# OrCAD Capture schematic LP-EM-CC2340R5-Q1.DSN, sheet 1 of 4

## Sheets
1 1_RF: size A3; title: LP-EM-CC2340R5
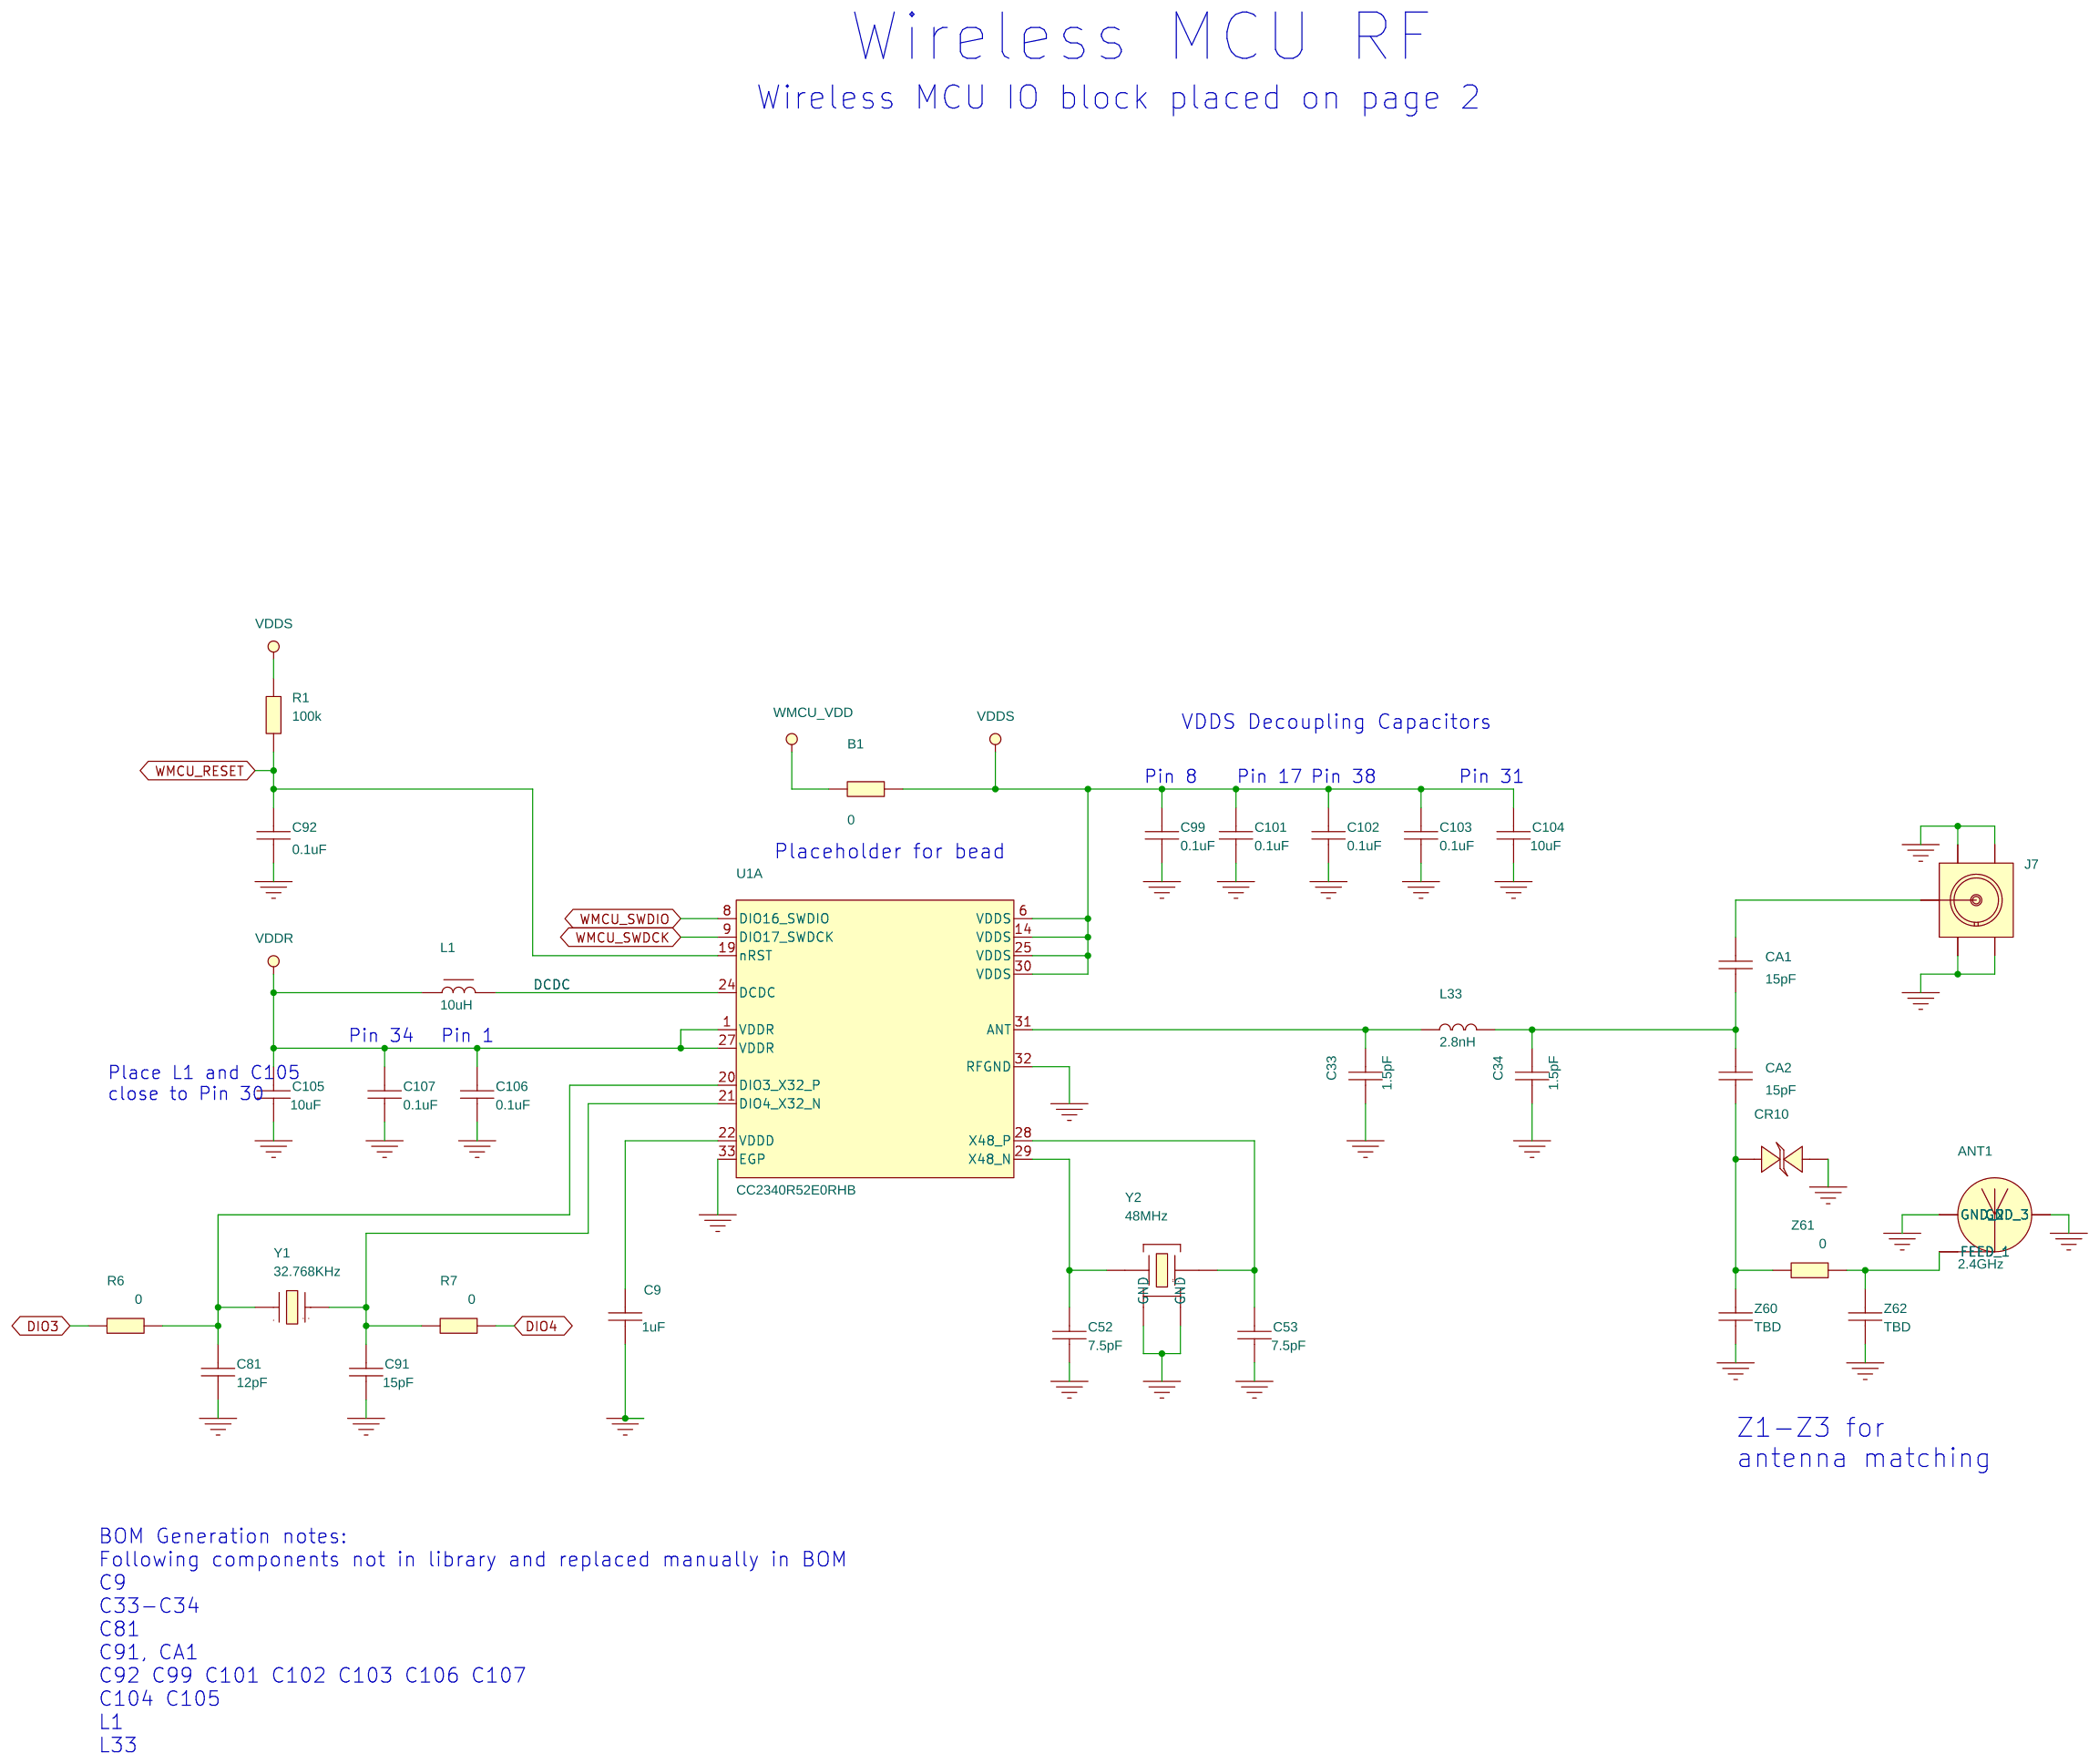
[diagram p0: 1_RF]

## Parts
sheet 1_RF
ANT1  2.4GHz  [ANTENNA_DN007AN]
B1  0  [RESC1608X55A2N]
C9  1uF  [CAPC1005X60B2N]
C33  1.5pF  [CAPC0603X35B2N]
C34  1.5pF  [CAPC0603X35B2N]
C52  7.5pF  [CAPC0603X35B2N]
C53  7.5pF  [CAPC0603X35B2N]
C81  12pF  [CAPC0603X35B2N]
C91  15pF  [CAPC0603X35B2N]
C92  0.1uF  [CAPC0603X35B2N]
C99  0.1uF  [CAPC0603X35B2N]
C101  0.1uF  [CAPC0603X35B2N]
C102  0.1uF  [CAPC0603X35B2N]
C103  0.1uF  [CAPC0603X35B2N]
C104  10uF  [CAPC1608X100A2N]
C105  10uF  [CAPC1608X100A2N]
C106  0.1uF  [CAPC0603X35B2N]
C107  0.1uF  [CAPC0603X35B2N]
CA1  15pF  [CAPC0603X35B2N]
CA2  15pF  [CAPC0603X35B2N]
CR10  TPD1E0B04DPY  [SON65P100X60X45-2A2N]
J7  SMA-10V21-TGG  [HUSTSAN_SMA10V21TGGAN]
L1  10uH  [INDC1608X100A2N]
L33  2.8nH  [INDC0603X33A2N]
R1  100k  [RESC0603X35B2N]
R6  0  [RESC0603X35B2N]
R7  0  [RESC0603X35B2N]
Y1  32.768KHz  [XTAL_TZ3359DAAO73_A2N]
Y2  48MHz  [OSCCC205X165X50-4A2N]
Z60  TBD  [CAPC0603X35B2N]
Z61  0  [RESC0603X35B2N]
Z62  TBD  [CAPC0603X35B2N]
sheet 2_Peripherals
U1  CC2340R52E0RHB  [QFNFC50P500X500X100-33B2N]  (sections A,B)

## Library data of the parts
ANT1 = ANTENNA_DN007: ANTENNA, NON COMPONENT, 2.4GHz INVERTED F ANTENNA, NOT APPLY; Additional Datasheet URL: N/A; AutoDoc File: http://notefied-dynamic-precision.com/DB/Apps/Desktop/Item/Object.aspx?id=85542; Budget Currency: N/A; Budget Price: N/A; CLASS: DISCRETE; Country of Origin: Missing Info; Datasheet URL: http://www.ti.com/; Datasheet URL 1: http://www.ti.com/lit/er/swrz002d/swrz002d.pdf; Datasheet URL 2: http://www.ti.com/lit/ds/symlink/cc2500.pdf; Definied Quality: INDUSTRIAL; Esd Level: HBM 500V; Exclusive for Customers: TEXAS INSTRUMENTS NORWAY; FPLIST: ANTENNA_DN007N,ANTENNA_DN007AN,; MPN: DN007; MPN Status: ACTIVE; MSL: N/A; MTBF: N/A; MTBF Standard: N/A; Manufacturer: TEXAS INSTRUMENTS; Mass: N/A; Max Oper Temp: +85DEGC; Maximum Operating Temperature: +85DEGC; Min Oper Temp: -40DEGC; Minimum Operating Temperature: -40DEGC; Mounting Type: NOT APPLY; NOTE Status: PREFERRED; NOTEfied URL: https://notefied-dynamic-precision.com/NOTEfiedWebInterface/part/show?partNumber=13-00347; Notes: Custom Item; Old Footprint: ANTENNA_DN007N,ANTENNA_DN007AN; Packing Size: N/A; Packing Type: Missing Info; Part Number: 13-00347; Part Type: Mechanic|ANTENNA|NON COMPONENT; ROHS: Not Applicable; Revision: R026; RoHS Status: LEADED; Status: Released; Texas Part Status: Under Review; Type: Mechanic; Vendor: TEXAS INSTRUMENTS; Vendor Part Number: DN007; Vendor Part Status: Active; WEIGHT: N/A
B1 = RESISTOR: RESISTOR, THICK FILM, 0, 0R/+0.05R, 1A, -55DEGC/+155DEGC, 0603, SMD; ALT_SYMBOLS: RESC1608X55A2L,RESC1608X55A2M; Additional Datasheet URL: https://www.koaspeer.com/products/resistors/general-purpose/rk73z/; Budgetary Price: 0.003 EUR; Country of Origin: China,Japan,Malaysia; Datasheet URL: https://www.koaspeer.com/pdfs/RK73Z.pdf; Lead Time: 46; Mass: 0.00214g; Maximum Operating Temperature: +155DEGC; Maximum Temperature Coefficient: N/A; Maximum Tolerance: +0.05R; Minimum Operating Temperature: -55DEGC; Minimum Temperature Coeficient: N/A; Minimum Tolerance: 0R; Mounting Type: SMD; NOTEfied URL: https://notefied-dynamic-precision.com/NOTEfiedWebInterface/part/show?partNumber=01-01788; PCB Package: 0603; Packing Size: 5000; Packing Type: Tape & Reel; Part Number: 01-01788; Part Type: Resistor|0603|JUMPER; ROHS: Exempt; Rated Current: 1A; Rated Power: 0.1; Rated Voltage: N/A; Resistor Type: THICK FILM; Revision: R048; Status: Released; Type: Resistor; Vendor: KOA SPEER; Vendor Part Number: RK73Z1JTTD; Vendor Part Status: Active
C9 = CAPACITOR: CAPACITOR, CERAMIC X7R, 1uF, 10V, -10%/+10%, -55DEGC/+125DEGC, 0402, SMD; Additional Datasheet URL: https://search.murata.co.jp/Ceramy/image/img/A01X/G101/ENG/GRM155Z71A105KE01-01A.pdf; Datasheet URL: https://www.murata.com/-/media/webrenewal/support/library/catalog/products/capacitor/ceramiccapacitor/c02e.ashx; Dielectric Type: X7R; Mass: 0.0016g; Maximum Operating Temperature: +125DEGC; Maximum Tolerance: +10%; Minimum Operating Temperature: -55DEGC; Minimum Tolerance: -10%; Mounting Type: SMD; NOTEfied URL: https://notefied-dynamic-precision.com/NOTEfiedWebInterface/part/show?partNumber=02-10417; PCB Package: 0402; Packing Size: 10000; Packing Type: Tape & Reel; Part Number: 02-10417; Part Type: Capacitor|CERAMIC|0402|STANDARD; REACH/SVHC Compliance: Compliant; REACH/SVHC Details: SVHC List Version Jul 08, 2021; REACH/SVHC Source: REACH Declaration; REACH/SVHC Status: Unaffected; ROHS: Compliant; Rated Voltage: 10V; Revision: R001; Status: Released; Texas Part Status: Under Review; Type: Capacitor; Vendor: MURATA; Vendor Part Number: GRM155Z71A105KE01D; Vendor Part Status: Active
C33 C34 = CAPACITOR: CAPACITOR, CERAMIC C0G/NP0, 0.9pF, 50V, -0.1pF/+0.1pF, -55DEGC/+125DEGC, 0201, SMD; ALT_SYMBOLS: CAPC0603X35B2L,CAPC0603X35B2M; Additional Datasheet URL: https://search.murata.co.jp/Ceramy/image/img/A01X/G101/ENG/GRM0335C1HR90BA01-01A.pdf; AutoDoc File: https://notefied-dynamic-precision.com/DB/Apps/Desktop/Item/Object.aspx?id=113355; BU Name: TEXAS INSTRUMENTS NORWAY; Budget Currency: EUR; Budget Price: 0.006; Budgetary Price: 0.00272 USD; Capacitance: 0.9pF; Country of Origin: Missing Info; Datasheet URL: https://www.murata.com/-/media/webrenewal/support/library/catalog/products/capacitor/ceramiccapacitor/c02e.ashx; Datasheet URL 1: http://psearch.murata.com/capacitor/product/GRM1555C1H1R0CA01%23.pdf; Datasheet URL 2: http://search.murata.co.jp/Ceramy/image/img/w_hinm/L0005E.pdf; Dielectric Type: C0G/NP0; Lead Time: 11; MPN: GRM1555C1H1R0CA01D; MPN Status: ACTIVE; Manufacturer: MURATA; Mass: 0.00033g; Max Oper Temp: +125DEGC; Max Tol: +0.25pF; Maximum Operating Temperature: +125DEGC; Maximum Tolerance: +0.1pF; Min Oper Temp: -55DEGC; Min Tol: -0.25pF; Minimum Operating Temperature: -55DEGC; Minimum Tolerance: -0.1pF; Mounting Type: SMD; NOTE Status: PREFERRED; NOTEfied URL: https://notefied-dynamic-precision.com/NOTEfiedWebInterface/part/show?partNumber=02-06123; Old Footprint: CAPC1005X60N; PCB Package: 0201; Packing Size: 50000; Packing Type: Tape & Reel; Part Number: 02-06123; Part Type: Capacitor|CERAMIC|0201|STANDARD; REACH/SVHC Compliance: Compliant; REACH/SVHC Details: SVHC List Version Jul 7, 2017; REACH/SVHC Source: REACH Declaration; REACH/SVHC Status: Unaffected; REACH/SVHC_COMPLIANCE: COMPLIANT; REACH/SVHC_DETAILS: SVHC LIST VERSION Dec 17, 2015; REACH/SVHC_SOURCE: REACH DECLARATION; REACH/SVHC_STATUS: UNAFFECTED; ROHS: Compliant; Rated Voltage: 50V; Revision: R027; RoHS Status: ROHS_COMPLIANT; Rtd Voltage: 50V; Status: Released; Texas Part Status: Under Review; Type: Capacitor; Vendor: MURATA; Vendor Part Number: GRM0335C1HR90BA01J; Vendor Part Status: Active; WEIGHT: 0.0016g
C52 C53 = CAPACITOR: CAPACITOR, CERAMIC C0G/NP0, 7.5pF, 50V, -0.1pF/+0.1pF, -55DEGC/+125DEGC, 0201, SMD; ALT_SYMBOLS: CAPC0603X35B2L,CAPC0603X35B2M; Additional Datasheet URL: https://search.murata.co.jp/Ceramy/image/img/A01X/G101/ENG/GRM0335C1H7R5BA01-01A.pdf; Budgetary Price: 0.00221 USD; Country of Origin: Missing Info; Datasheet URL: https://www.murata.com/-/media/webrenewal/support/library/catalog/products/capacitor/mlcc/c02e.ashx?la=en-gb; Dielectric Type: C0G/NP0; Lead Time: 11; Mass: 0.00033g; Maximum Operating Temperature: +125DEGC; Maximum Tolerance: +0.1pF; Minimum Operating Temperature: -55DEGC; Minimum Tolerance: -0.1pF; Mounting Type: SMD; NOTEfied URL: https://notefied-dynamic-precision.com/NOTEfiedWebInterface/part/show?partNumber=02-06189; PCB Package: 0201; Packing Size: 50000; Packing Type: Tape & Reel; Part Number: 02-06189; Part Type: Capacitor|CERAMIC|0201|STANDARD; REACH/SVHC Compliance: Compliant; REACH/SVHC Details: SVHC List Version Jul 7, 2017; REACH/SVHC Source: REACH Declaration; REACH/SVHC Status: Unaffected; ROHS: Compliant; Rated Voltage: 50V; Revision: R025; Status: Released; Texas Part Status: Under Review; Type: Capacitor; Vendor: MURATA; Vendor Part Number: GRM0335C1H7R5BA01J; Vendor Part Status: Active
C81 = CAPACITOR: CAPACITOR, CERAMIC C0G/NP0, 12pF, 50V, -2%/+2%, -55DEGC/+125DEGC, 0201, SMD; ALT_SYMBOLS: CAPC0603X35B2L,CAPC0603X35B2M; Additional Datasheet URL: https://search.murata.co.jp/Ceramy/image/img/A01X/G101/ENG/GRM0335C1H120GA01-01A.pdf; AutoDoc File: https://notefied-dynamic-precision.com/DB/Apps/Desktop/Item/Object.aspx?id=113345; BU Name: TEXAS INSTRUMENTS NORWAY; Budget Currency: EUR; Budget Price: 0.007; Budgetary Price: 0.00506 USD; Datasheet URL: https://www.murata.com/-/media/webrenewal/support/library/catalog/products/capacitor/ceramiccapacitor/c02e.ashx?la=en-gb&cvid=20210120024548000000; Datasheet URL 1: http://psearch.murata.com/capacitor/product/GRM1555C1H120JA01%23.pdf; Datasheet URL 2: http://search.murata.co.jp/Ceramy/image/img/w_hinm/L0005E.pdf; Definied Quality: INDUSTRIAL; Dielectric Type: C0G/NP0; Esd Level: N/A; Lead Time: 23; LifeCycle Status: ACTIVE; MPN: CAPACITOR_0402_12pF_C0G/NP0_M_+/-5%_50V; MPN Status: ACTIVE; MSL: N/A; MTBF: N/A; MTBF Standard: N/A; Manufacturer: MANUFACTURER SELECTION; Mass: 0.00033g; Max Oper Temp: +125DEGC; Max Tol: +5%; Maximum Operating Temperature: +125DEGC; Maximum Tolerance: +2%; Min Oper Temp: -55DEGC; Min Tol: -5%; Minimum Operating Temperature: -55DEGC; Minimum Tolerance: -2%; Mounting Type: SMD; NOTE Status: PREFERRED; NOTEfied URL: https://notefied-dynamic-precision.com/NOTEfiedWebInterface/part/show?partNumber=02-10307; Old Footprint: CAPC1005X60N; PCB Package: 0201; Packing Size: 15000; Packing Type: Tape & Reel; Part Number: 02-10307; Part Type: Capacitor|CERAMIC|0201|STANDARD; REACH/SVHC Compliance: Compliant; REACH/SVHC Details: SVHC List Version Jan 19, 2021; REACH/SVHC Source: REACH Declaration; REACH/SVHC Status: Unaffected; REACH/SVHC_COMPLIANCE: COMPLIANT; REACH/SVHC_DETAILS: SVHC LIST VERSION Dec 17, 2015; REACH/SVHC_SOURCE: REACH DECLARATION; REACH/SVHC_STATUS: UNAFFECTED; ROHS: Compliant; Rated Voltage: 50V; Revision: R001; RoHS Status: ROHS_COMPLIANT; Rtd Voltage: 50V; Status: Released; Texas Part Status: Under Review; Type: Capacitor; Vendor: MURATA; Vendor Part Number: GRM0335C1H120GA01D; Vendor Part Status: Active; WEIGHT: 0.0016g
C91 = CAPACITOR: CAPACITOR, CERAMIC C0G/NP0, 15pF, 50V, -2%/+2%, -55DEGC/+125DEGC, 0201, SMD; ALT_SYMBOLS: CAPC0603X35B2L,CAPC0603X35B2M; Additional Datasheet URL: https://search.murata.co.jp/Ceramy/image/img/A01X/G101/ENG/GRM0335C1H150GA01-01A.pdf; AutoDoc File: https://notefied-dynamic-precision.com/DB/Apps/Desktop/Item/Object.aspx?id=114571; BU Name: TEXAS INSTRUMENTS NORWAY; Budget Currency: EUR; Budget Price: 0.006; Budgetary Price: 0.0032 USD; Client Status: UNDER_REVIEW; Datasheet URL: https://www.murata.com/-/media/webrenewal/support/library/catalog/products/capacitor/mlcc/c02e.ashx?la=en-gb; Datasheet URL 1: http://psearch.murata.com/capacitor/product/GRM1555C1H150JA01%23.pdf; Datasheet URL 2: http://psearch.en.murata.com/capacitor/product/GRM1555C1H150JA01%23.html; Definied Quality: INDUSTRIAL; Dielectric Type: C0G/NP0; Esd Level: N/A; Lead Time: 11; LifeCycle Status: ACTIVE; MPN: CAPACITOR_0402_12pF_C0G/NP0_M_+/-5%_50V; MPN Status: ACTIVE; MSL: N/A; MTBF: N/A; MTBF Standard: N/A; Manufacturer: MANUFACTURER SELECTION; Mass: 0.00033g; Max Oper Temp: +125DEGC; Max Tol: +5%; Maximum Operating Temperature: +125DEGC; Maximum Tolerance: +2%; Min Oper Temp: -55DEGC; Min Tol: -5%; Minimum Operating Temperature: -55DEGC; Minimum Tolerance: -2%; Mounting Type: SMD; NOTE Status: PREFERRED; NOTEfied URL: https://notefied-dynamic-precision.com/NOTEfiedWebInterface/part/show?partNumber=02-09323; Old Footprint: CAPC1005X60N; PCB Package: 0201; Packing Size: 15000; Packing Type: Tape & Reel; Part Number: 02-09323; Part Type: Capacitor|CERAMIC|0201|STANDARD; REACH/SVHC Compliance: Compliant; REACH/SVHC Details: SVHC List Version Jan 15, 2019; REACH/SVHC Source: REACH Declaration; REACH/SVHC Status: Unaffected; REACH/SVHC_COMPLIANCE: COMPLIANT; REACH/SVHC_DETAILS: SVHC List Version Jan 12, 2017; REACH/SVHC_SOURCE: REACH DECLARATION; REACH/SVHC_STATUS: UNAFFECTED; ROHS: Compliant; Rated Voltage: 50V; Revision: R008; RoHS Status: ROHS_COMPLIANT; Rtd Voltage: 50V; Status: Released; Texas Part Status: Under Review; Type: Capacitor; Vendor: MURATA; Vendor Part Number: GRM0335C1H150GA01D; Vendor Part Status: Active; WEIGHT: 0.0016g
C92 = CAPACITOR: CAPACITOR, CERAMIC X7S, 0.1uF, 10V, -10%/+10%, -55DEGC/+125DEGC, 0201, SMD; ALT_SYMBOLS: CAPC0603X35B2L,CAPC0603X35B2M; Additional Datasheet URL: https://search.murata.co.jp/Ceramy/image/img/A01X/G101/ENG/GRM033C71A104KE14-01A.pdf; AutoDoc File: https://notefied-dynamic-precision.com/DB/Apps/Desktop/Item/Object.aspx?id=115293; BU Name: TEXAS INSTRUMENTS NORWAY; Budgetary Price: 0.01328 USD; Client Status: UNDER_REVIEW; Datasheet URL: https://www.murata.com/-/media/webrenewal/support/library/catalog/products/capacitor/ceramiccapacitor/c02e.ashx?la=en-gb; Datasheet URL 1: http://psearch.en.murata.com/capacitor/product/GRM155R71E104KE14%23.pdf; Datasheet URL 2: http://search.murata.co.jp/Ceramy/image/img/w_hinm/L0005E.pdf; Dielectric Type: X7S; Lead Time: 23; LifeCycle Status: ACTIVE; MPN: GRM155R70J104KA01D; MPN Status: ACTIVE; Manufacturer: MURATA; Mass: 0.00033g; Max Oper Temp: +125DEGC; Max Tol: +10%; Maximum Operating Temperature: +125DEGC; Maximum Tolerance: +10%; Min Oper Temp: -55DEGC; Min Tol: -10%; Minimum Operating Temperature: -55DEGC; Minimum Tolerance: -10%; Mounting Type: SMD; NOTE Status: PREFERRED; NOTEfied URL: https://notefied-dynamic-precision.com/NOTEfiedWebInterface/part/show?partNumber=02-10308; Old Footprint: CAPC1005X60N,0402; PCB Package: 0201; Packing Size: 15000; Packing Type: Tape & Reel; Part Number: 02-10308; Part Type: Capacitor|CERAMIC|0201|STANDARD; REACH/SVHC Compliance: Compliant; REACH/SVHC Details: SVHC List Version Jan 19, 2021; REACH/SVHC Source: REACH Declaration; REACH/SVHC Status: Unaffected; REACH/SVHC_COMPLIANCE: COMPLIANT; REACH/SVHC_DETAILS: SVHC LIST VERSION Jun 20, 2016; REACH/SVHC_SOURCE: REACH DECLARATION; REACH/SVHC_STATUS: UNAFFECTED; ROHS: Compliant; Rated Voltage: 10V; Revision: R001; RoHS Status: ROHS_COMPLIANT; Rtd Voltage: 25V; Status: Released; Texas Part Status: Under Review; Type: Capacitor; Vendor: MURATA; Vendor Part Number: GRM033C71A104KE14D; Vendor Part Status: Active; WEIGHT: 0.0016g
C99 C101-C103 C106 C107 = CAPACITOR: CAPACITOR, CERAMIC X7S, 0.1uF, 10V, -10%/+10%, -55DEGC/+125DEGC, 0201, SMD; ALT_SYMBOLS: CAPC0603X35B2L,CAPC0603X35B2M; Additional Datasheet URL: https://search.murata.co.jp/Ceramy/image/img/A01X/G101/ENG/GRM033C71A104KE14-01A.pdf; AutoDoc File: https://notefied-dynamic-precision.com/DB/Apps/Desktop/Item/Object.aspx?id=115293; BU Name: TEXAS INSTRUMENTS NORWAY; Budgetary Price: 0.01328 USD; Client Status: UNDER_REVIEW; Datasheet URL: https://www.murata.com/-/media/webrenewal/support/library/catalog/products/capacitor/ceramiccapacitor/c02e.ashx; Datasheet URL 1: http://psearch.en.murata.com/capacitor/product/GRM155R71E104KE14%23.pdf; Datasheet URL 2: http://search.murata.co.jp/Ceramy/image/img/w_hinm/L0005E.pdf; Dielectric Type: X7S; Lead Time: 23; LifeCycle Status: ACTIVE; MPN: GRM155R70J104KA01D; MPN Status: ACTIVE; Manufacturer: MURATA; Mass: 0.00033g; Max Oper Temp: +125DEGC; Max Tol: +10%; Maximum Operating Temperature: +125DEGC; Maximum Tolerance: +10%; Min Oper Temp: -55DEGC; Min Tol: -10%; Minimum Operating Temperature: -55DEGC; Minimum Tolerance: -10%; Mounting Type: SMD; NOTE Status: PREFERRED; NOTEfied URL: https://notefied-dynamic-precision.com/NOTEfiedWebInterface/part/show?partNumber=02-10308; Old Footprint: CAPC1005X60N,0402; PCB Package: 0201; Packing Size: 15000; Packing Type: Tape & Reel; Part Number: 02-10308; Part Type: Capacitor|CERAMIC|0201|STANDARD; REACH/SVHC Compliance: Compliant; REACH/SVHC Details: SVHC List Version Jan 19, 2021; REACH/SVHC Source: REACH Declaration; REACH/SVHC Status: Unaffected; REACH/SVHC_COMPLIANCE: COMPLIANT; REACH/SVHC_DETAILS: SVHC LIST VERSION Jun 20, 2016; REACH/SVHC_SOURCE: REACH DECLARATION; REACH/SVHC_STATUS: UNAFFECTED; ROHS: Compliant; Rated Voltage: 10V; Revision: R003; RoHS Status: ROHS_COMPLIANT; Rtd Voltage: 25V; Status: Released; Texas Part Status: Under Review; Type: Capacitor; Vendor: MURATA; Vendor Part Number: GRM033C71A104KE14D; Vendor Part Status: Active; WEIGHT: 0.0016g
C104 = CAPACITOR: CAPACITOR, CERAMIC X7R, 10uF, 10V, -10%/+10%, -55DEGC/+125DEGC, 0603, SMD; ALT_SYMBOLS: CAPC1608X100A2L,CAPC1608X100A2M; Additional Datasheet URL: https://search.murata.co.jp/Ceramy/image/img/A01X/G101/ENG/GRM188Z71A106KA73-01A.pdf; Datasheet URL: https://www.murata.com/-/media/webrenewal/support/library/catalog/products/capacitor/ceramiccapacitor/c02e.ashx; Dielectric Type: X7R; Mass: 0.0091g; Maximum Operating Temperature: +125DEGC; Maximum Tolerance: +10%; Minimum Operating Temperature: -55DEGC; Minimum Tolerance: -10%; Mounting Type: SMD; NOTEfied URL: https://notefied-dynamic-precision.com/NOTEfiedWebInterface/part/show?partNumber=02-10418; PCB Package: 0603; Packing Size: 4000; Packing Type: Tape & Reel; Part Number: 02-10418; Part Type: Capacitor|CERAMIC|0603|STANDARD; REACH/SVHC Compliance: Compliant; REACH/SVHC Details: SVHC List Version Jul 08, 2021; REACH/SVHC Source: REACH Declaration; REACH/SVHC Status: Unaffected; ROHS: Compliant; Rated Voltage: 10V; Revision: R001; Status: Released; Texas Part Status: Under Review; Type: Capacitor; Vendor: MURATA; Vendor Part Number: GRM188Z71A106KA73D; Vendor Part Status: Active
C105 = CAPACITOR: CAPACITOR, CERAMIC X7R, 10uF, 10V, -10%/+10%, -55DEGC/+125DEGC, 0603, SMD; ALT_SYMBOLS: CAPC1608X100A2L,CAPC1608X100A2M; Additional Datasheet URL: https://search.murata.co.jp/Ceramy/image/img/A01X/G101/ENG/GRM188Z71A106KA73-01A.pdf; Datasheet URL: https://www.murata.com/-/media/webrenewal/support/library/catalog/products/capacitor/ceramiccapacitor/c02e.ashx; Dielectric Type: X7R; Mass: 0.0091g; Maximum Operating Temperature: +125DEGC; Maximum Tolerance: +10%; Minimum Operating Temperature: -55DEGC; Minimum Tolerance: -10%; Mounting Type: SMD; NOTEfied URL: https://notefied-dynamic-precision.com/NOTEfiedWebInterface/part/show?partNumber=02-10418; PCB Package: 0603; Packing Size: 4000; Packing Type: Tape & Reel; Part Number: 02-10418; Part Type: Capacitor|CERAMIC|0603|STANDARD; REACH/SVHC Compliance: Compliant; REACH/SVHC Details: SVHC List Version Jul 08, 2021; REACH/SVHC Source: REACH Declaration; REACH/SVHC Status: Unaffected; ROHS: Compliant; Rated Voltage: 10V; Revision: R002; Status: Released; Texas Part Status: Under Review; Type: Capacitor; Vendor: MURATA; Vendor Part Number: GRM188Z71A106KA73D; Vendor Part Status: Active
CA1 CA2 = CAPACITOR: CAPACITOR, CERAMIC C0G/NP0, 15pF, 50V, -2%/+2%, -55DEGC/+125DEGC, 0201, SMD; ALT_SYMBOLS: CAPC0603X35B2L,CAPC0603X35B2M; Additional Datasheet URL: https://search.murata.co.jp/Ceramy/image/img/A01X/G101/ENG/GRM0335C1H150GA01-01A.pdf; AutoDoc File: https://notefied-dynamic-precision.com/DB/Apps/Desktop/Item/Object.aspx?id=113345; BU Name: TEXAS INSTRUMENTS NORWAY; Budget Currency: EUR; Budget Price: 0.007; Budgetary Price: 0.0032 USD; Datasheet URL: https://www.murata.com/-/media/webrenewal/support/library/catalog/products/capacitor/ceramiccapacitor/c02e.ashx; Datasheet URL 1: http://psearch.murata.com/capacitor/product/GRM1555C1H120JA01%23.pdf; Datasheet URL 2: http://search.murata.co.jp/Ceramy/image/img/w_hinm/L0005E.pdf; Definied Quality: INDUSTRIAL; Dielectric Type: C0G/NP0; Esd Level: N/A; Lead Time: 11; LifeCycle Status: ACTIVE; MPN: CAPACITOR_0402_12pF_C0G/NP0_M_+/-5%_50V; MPN Status: ACTIVE; MSL: N/A; MTBF: N/A; MTBF Standard: N/A; Manufacturer: MANUFACTURER SELECTION; Mass: 0.00033g; Max Oper Temp: +125DEGC; Max Tol: +5%; Maximum Operating Temperature: +125DEGC; Maximum Tolerance: +2%; Min Oper Temp: -55DEGC; Min Tol: -5%; Minimum Operating Temperature: -55DEGC; Minimum Tolerance: -2%; Mounting Type: SMD; NOTE Status: PREFERRED; NOTEfied URL: https://notefied-dynamic-precision.com/NOTEfiedWebInterface/part/show?partNumber=02-09323; Old Footprint: CAPC1005X60N; PCB Package: 0201; Packing Size: 15000; Packing Type: Tape & Reel; Part Number: 02-09323; Part Type: Capacitor|CERAMIC|0201|STANDARD; REACH/SVHC Compliance: Compliant; REACH/SVHC Details: SVHC List Version Jan 15, 2019; REACH/SVHC Source: REACH Declaration; REACH/SVHC Status: Unaffected; REACH/SVHC_COMPLIANCE: COMPLIANT; REACH/SVHC_DETAILS: SVHC LIST VERSION Dec 17, 2015; REACH/SVHC_SOURCE: REACH DECLARATION; REACH/SVHC_STATUS: UNAFFECTED; ROHS: Compliant; Rated Voltage: 50V; Revision: R010; RoHS Status: ROHS_COMPLIANT; Rtd Voltage: 50V; Status: Released; Texas Part Status: Under Review; Type: Capacitor; Vendor: MURATA; Vendor Part Number: GRM0335C1H150GA01D; Vendor Part Status: Active; WEIGHT: 0.0016g
CR10 = DIODE_TVS_BIDIR_S: DIODE, PROTECTION, TVS, BID, 6.7V, 15W, -40DEGC/+125DEGC, X1SON2, SMD; Additional Datasheet URL: https://www.ti.com/lit/ml/mpss034c/mpss034c.pdf; AutoDoc File: https://notefied-dynamic-precision.com/DB/Apps/Desktop/Item/Object.aspx?id=118028; BU Name: DYNAMIC PRECISION GDANSK; Budget Currency: USD; Budget Price: 0.08; Budgetary Price: 0.144 USD; Client Status: UNDER_REVIEW; Datasheet URL: https://www.ti.com/lit/gpn/tpd1e0b04; Datasheet URL 1: http://www.ti.com/lit/ds/symlink/tpd1e0b04.pdf; Datasheet URL 2: http://www.ti.com/lit/ml/mpss034c/mpss034c.pdf; Lead Time: 12; Mass: 0.0031g; Max Oper Temp: +125DEGC; Maximum Operating Temperature: +125DEGC; Min Oper Temp: -40DEGC; Minimum Operating Temperature: -40DEGC; Mounting Type: SMD; NOTEfied URL: https://notefied-dynamic-precision.com/NOTEfiedWebInterface/part/show?partNumber=14-06704; PCB Package: SON2; Packing Size: 10000; Packing Type: Tape & Reel; Part Number: 14-06704; Part Type: Diode|PROTECTION; REACH/SVHC Compliance: Compliant; REACH/SVHC Details: SVHC List Version Jan 12, 2017; REACH/SVHC Source: REACH Declaration; REACH/SVHC Status: Unaffected; ROHS: Compliant; Rated Power: 15W; Rated Voltage: 6.7V; Revision: R023; RoHS Status: ROHS_COMPLIANT; Rtd Power: 15W; Rtd Voltage: 6.7V; Status: Released; Texas Part Status: Under Review; Type: Diode; Vendor: TEXAS INSTRUMENTS; Vendor Part Number: TPD1E0B04DPYR; Vendor Part Status: Active; Weight: 0.0031g
J7 = CONN_COAX_1_4: CONNECTOR, COAX, RF, FEMALE, STRAIGHT, 1 PIN, SMD; ALT_SYMBOLS: HUSTSAN_SMA10V21TGGL,HUSTSAN_SMA10V21TGGM; Additional Datasheet URL: http://www.hustsan.com.tw/cgi-bin/productfn/pdt_detail_lst.pl?ProdID=143; AutoDoc File: https://notefied-dynamic-precision.com/DB/Apps/Desktop/Item/Object.aspx?id=84956; BU Name: DYNAMIC PRECISION GDANSK; Budget Currency: N/A; Budget Price: N/A; Client Status: UNDER_REVIEW; Country of Origin: Taiwan; Datasheet URL: http://www.hustsan.com.tw/uploaddir/product/SMA-10V21.pdf; Datasheet URL 1: http://www.hustsan.com.tw/uploaddir/product/SMA-10V21.pdf; Datasheet URL 2: http://www.hustsan.com.tw/cgi-bin/productfn/pdt_detail_lst.pl?ProdID=143; FPLIST: HUSTSAN_SMA10V21TGGAN,HUSTSAN_SMA10V21TGGN; Mass: N/A; Mounting Type: SMD; NOTEfied URL: https://notefied-dynamic-precision.com/NOTEfiedWebInterface/part/show?partNumber=06-02188; No Of Pos: 1; Number of Positions: 1; Packing Size: 350; Packing Type: Tape & Reel; Part Number: 06-02188; Part Type: Connector|COAX|RF; REACH/SVHC Compliance: Compliant; REACH/SVHC Details: SVHC List Version Jun 20, 2016; REACH/SVHC Source: REACH Declaration; REACH/SVHC Status: Unaffected; REACH/SVHC_COMPLIANCE: COMPLIANT; REACH/SVHC_DETAILS: SVHC LIST VERSION Jan 12, 2016; REACH/SVHC_SOURCE: REACH DECLARATION; REACH/SVHC_STATUS: UNAFFECTED; ROHS: Compliant; Revision: R011; RoHS Status: ROHS_COMPLIANT; Status: Released; Texas Part Status: Under Review; Type: Connector; Vendor: HUS-TSAN; Vendor Part Status: Active; Weight: N/A
L1 = IND_CORE: INDUCTOR, STANDARD, CHIP, FERRITE CORE, 10uH, -20%/+20%, 0.1A, -55DEGC/+125DEGC, 0603, SMD; ALT_SYMBOLS: INDC1608X100A2L,INDC1608X100A2M; Additional Datasheet URL: N/A; Datasheet URL: https://search.murata.co.jp/Ceramy/image/img/P02/JELF243B-0086.pdf; Frequency: 32MHz; Mass: 0.005g; Maximum Operating Temperature: +125DEGC; Maximum Tolerance: +20%; Minimum Operating Temperature: -55DEGC; Minimum Tolerance: -20%; Mounting Type: SMD; NOTEfied URL: https://notefied-dynamic-precision.com/NOTEfiedWebInterface/part/show?partNumber=03-08367; PCB Package: 0603; Packing Size: 4000; Packing Type: Tape & Reel; Part Number: 03-08367; Part Type: Inductor|STANDARD|CHIP|0603; REACH/SVHC Compliance: Missing Info; REACH/SVHC Details: Jul 08, 2021 (219); REACH/SVHC Source: N/A; REACH/SVHC Status: Unaffected; ROHS: Compliant; Resistance: 1.05; Revision: R002; Status: Released; Texas Part Status: Under Review; Type: Inductor; Vendor: MURATA; Vendor Part Number: LQM18DN100M70L; Vendor Part Status: Active
L33 = INDUCTOR: INDUCTOR, RF, CHIP, NON-MAGNETIC CORE, 2.8nH, -0.1nH/+0.1nH, 0.5A, -55DEGC/+125DEGC, 0201, SMD; ALT_SYMBOLS: INDC0603X33A2L,INDC0603X33A2M; Additional Datasheet URL: https://search.murata.co.jp/Ceramy/image/img/P02/JELF243C-0015.pdf; Country of Origin: Missing Info; Datasheet URL: https://www.murata.com/-/media/webrenewal/support/library/catalog/products/inductor/chip/o05e.ashx; Frequency: 9.5GHz; Mass: 0.0002g; Maximum Operating Temperature: +125DEGC; Maximum Tolerance: +0.1nH; Minimum Operating Temperature: -55DEGC; Minimum Tolerance: -0.1nH; Mounting Type: SMD; NOTEfied URL: https://notefied-dynamic-precision.com/NOTEfiedWebInterface/part/show?partNumber=03-06931; PCB Package: 0201; Packing Size: 50000; Packing Type: Tape & Reel; Part Number: 03-06931; Part Type: Inductor|RF|CHIP|0201; ROHS: Compliant; Resistance: 0.2; Revision: R022; Status: Released; Texas Part Status: Under Review; Type: Inductor; Vendor: MURATA; Vendor Part Number: LQP03TN2N8B02J; Vendor Part Status: Active
R1 = RESISTOR: RESISTOR, THICK FILM, 100k, -5%/+5%, 0.05W, 30V, -55DEGC/+155DEGC, 0201, SMD; ALT_SYMBOLS: RESC0603X35B2L,RESC0603X35B2M; Additional Datasheet URL: N/A; Budgetary Price: 0.005 EUR; Country of Origin: Taiwan; Datasheet URL: https://www.vishay.com/docs/20052/crcw0201e3.pdf; Lead Time: 20; Mass: 0.00017g; Maximum Operating Temperature: +155DEGC; Maximum Temperature Coefficient: +200PPM/DEGC; Maximum Tolerance: +5%; Minimum Operating Temperature: -55DEGC; Minimum Temperature Coeficient: -200PPM/DEGC; Minimum Tolerance: -5%; Mounting Type: SMD; NOTEfied URL: https://notefied-dynamic-precision.com/NOTEfiedWebInterface/part/show?partNumber=01-04220; PCB Package: 0201; Packing Size: 10000; Packing Type: Tape & Reel; Part Number: 01-04220; Part Type: Resistor|0201|STANDARD; REACH/SVHC Compliance: Compliant; REACH/SVHC Details: SVHC List Version Dec 17, 2015; REACH/SVHC Source: Material Declaration; REACH/SVHC Status: Unaffected; ROHS: Exempt; Rated Current: N/A; Rated Power: 0.05W; Rated Voltage: 30V; Resistor Type: THICK FILM; Revision: R008; Status: Released; Type: Resistor; Vendor: VISHAY; Vendor Part Number: CRCW0201100KJNED; Vendor Part Status: Active
R6 R7 Z61 = RESISTOR: RESISTOR, THICK FILM, 0, 0R/+0.05R, 0.5A, -55DEGC/+125DEGC, 0201, SMD; ALT_SYMBOLS: RESC0603X35B2L,RESC0603X35B2M; Additional Datasheet URL: http://www.koaspeer.com/pdfs/Appendix_A.pdf; Budgetary Price: 0.012 EUR; Country of Origin: Missing Info; Datasheet URL: http://www.koaspeer.com/pdfs/RK73Z.pdf; Lead Time: 14; Mass: 0.00014g; Maximum Operating Temperature: +125DEGC; Maximum Temperature Coefficient: N/A; Maximum Tolerance: +0.05R; Minimum Operating Temperature: -55DEGC; Minimum Temperature Coeficient: N/A; Minimum Tolerance: 0R; Mounting Type: SMD; NOTEfied URL: https://notefied-dynamic-precision.com/NOTEfiedWebInterface/part/show?partNumber=01-18293; PCB Package: 0201; Packing Size: 10000; Packing Type: Tape & Reel; Part Number: 01-18293; Part Type: Resistor|0201|JUMPER; ROHS: Exempt; Rated Current: 0.5A; Rated Power: N/A; Rated Voltage: N/A; Resistor Type: THICK FILM; Revision: R013; Status: Released; Type: Resistor; Vendor: KOA SPEER; Vendor Part Number: RK73Z1HTTC; Vendor Part Status: Active
Y1 = XTAL: CRYSTAL, RESONATOR, 32.768KHz, -380PPM/+380PPM, -40DEGC/+125DEGC, SMD; ALT_SYMBOLS: XTAL_TZ3359DAAO73_A2L,XTAL_TZ3359DAAO73_A2M; Capacitance: 7pF; Datasheet URL: https://www.taisaw.com/en/product.php?pc=7; Exclusive for Customers: TEXAS INSTRUMENTS NORWAY; Maximum Operating Temperature: +125DEGC; Maximum Stability: +380PPM; Maximum Tolerance: +20PPM; Minimum Operating Temperature: -40DEGC; Minimum Stability: -380PPM; Minimum Tolerance: -20PPM; Mounting Type: SMD; NOTEfied URL: https://notefied-dynamic-precision.com/NOTEfiedWebInterface/part/show?partNumber=12-01593; Notes: Non-standard part/non-catalogue part. Created on the basis of documentation provided by the customer (Texas Instruments).; Packing Size: 5000; Packing Type: Tape & Reel; Part Number: 12-01593; Part Type: Crystal|RESONATOR; REACH/SVHC Compliance: Missing Info; REACH/SVHC Details: N/A; REACH/SVHC Source: N/A; REACH/SVHC Status: Missing Info; ROHS: Compliant; Revision: R001; Status: Released; Texas Part Status: Under Review; Type: Crystal; Vendor: TAI-SAW; Vendor Part Number: TZ3359DAAO73; Vendor Part Status: Active
Y2 = XTAL_4PINS_1_3: CRYSTAL, RESONATOR, 48MHz, -30PPM/+30PPM, -40DEGC/+125DEGC, SMD; ALT_SYMBOLS: OSCCC205X165X50-4A2L,OSCCC205X165X50-4A2M; Capacitance: 7pF; Datasheet URL: https://www.taisaw.com/en/product.php?pc=7; Exclusive for Customers: TEXAS INSTRUMENTS NORWAY; Mass: 0.0057g; Maximum Operating Temperature: +125DEGC; Maximum Stability: +30PPM; Maximum Tolerance: +5PPM; Minimum Operating Temperature: -40DEGC; Minimum Stability: -30PPM; Minimum Tolerance: -5PPM; Mounting Type: SMD; NOTEfied URL: https://notefied-dynamic-precision.com/NOTEfiedWebInterface/part/show?partNumber=12-01592; Notes: Non-standard part/non-catalogue part. Created on the basis of documentation provided by the customer (Texas Instruments).; Packing Size: 3000; Packing Type: Tape & Reel; Part Number: 12-01592; Part Type: Crystal|RESONATOR; REACH/SVHC Compliance: Missing Info; REACH/SVHC Details: N/A; REACH/SVHC Source: N/A; REACH/SVHC Status: Missing Info; ROHS: Compliant; Revision: R001; Status: Released; Texas Part Status: Under Review; Type: Crystal; Vendor: TAI-SAW; Vendor Part Number: TZ3908AAAO43; Vendor Part Status: Active
Z60 Z62 = CAPACITOR: CAPACITOR, CERAMIC C0G/NP0, 12pF, 50V, -2%/+2%, -55DEGC/+125DEGC, 0201, SMD; ALT_SYMBOLS: CAPC0603X35B2L,CAPC0603X35B2M; Additional Datasheet URL: https://search.murata.co.jp/Ceramy/image/img/A01X/G101/ENG/GRM0335C1H120GA01-01A.pdf; AutoDoc File: https://notefied-dynamic-precision.com/DB/Apps/Desktop/Item/Object.aspx?id=113344; BU Name: TEXAS INSTRUMENTS NORWAY; Budget Currency: USD; Budget Price: 0.00589; Budgetary Price: 0.00506 USD; Capacitance: 12pF; Datasheet URL: https://www.murata.com/-/media/webrenewal/support/library/catalog/products/capacitor/ceramiccapacitor/c02e.ashx; Datasheet URL 1: N/A; Datasheet URL 2: N/A; Dielectric Type: C0G/NP0; Lead Time: 23; MPN: CAPACITOR_0402_DNM_N/A_M; MPN Status: ACTIVE; Manufacturer: Manufacturer selection; Mass: 0.00033g; Max Oper Temp: +125DEGC; Maximum Operating Temperature: +125DEGC; Maximum Tolerance: +2%; Min Oper Temp: -55DEGC; Minimum Operating Temperature: -55DEGC; Minimum Tolerance: -2%; Mounting Type: SMD; NOTE Status: PREFERRED; NOTEfied URL: https://notefied-dynamic-precision.com/NOTEfiedWebInterface/part/show?partNumber=02-10307; Old Footprint: CAPC1005X60N; PCB Package: 0201; Packing Size: 15000; Packing Type: Tape & Reel; Part Number: 02-10307; Part Type: Capacitor|CERAMIC|0201|STANDARD; REACH/SVHC Compliance: Compliant; REACH/SVHC Details: SVHC List Version Jan 19, 2021; REACH/SVHC Source: REACH Declaration; REACH/SVHC Status: Unaffected; ROHS: Compliant; Rated Voltage: 50V; Revision: R002; RoHS Status: MISSING_INFO; Status: Released; Texas Part Status: Under Review; Type: Capacitor; Vendor: MURATA; Vendor Part Number: GRM0335C1H120GA01D; Vendor Part Status: Active; Weight: N/A
U1 = IC_CC2340R52E0RHB_VQFN32: IC, CUSTOM, TEXAS INSTRUMENTS, CC2340R52E0RHB, VQFN32-EP, SMD; ALT_SYMBOLS: QFNFC50P500X500X100-33B2L,QFNFC50P500X500X100-33B2M; Additional Datasheet URL: N/A; Datasheet URL: N/A; Exclusive for Customers: TEXAS INSTRUMENTS NORWAY; Mass: N/A; Maximum Operating Temperature: N/A; Minimum Operating Temperature: N/A; Mounting Type: SMD; NOTEfied URL: https://notefied-dynamic-precision.com/NOTEfiedWebInterface/part/show?partNumber=18-37032; Notes: Custom item; PCB Package: VQFN32-EP; Packing Size: N/A; Packing Type: Missing Info; Part Number: 18-37032; Part Type: IC|CUSTOM; REACH/SVHC Compliance: Missing Info; REACH/SVHC Details: N/A; REACH/SVHC Source: N/A; REACH/SVHC Status: Missing Info; ROHS: Missing Info; Revision: R001; Status: Released; Texas Part Status: Under Review; Type: IC; Vendor: TEXAS INSTRUMENTS; Vendor Part Status: Preliminary

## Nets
GND: ANT1.2(GND) ANT1.3(GND) C9.2 C33.1 C34.1 C52.2 C53.2 C81.2 C91.2 C92.2 C99.2 C101.2 C102.2 C103.2 C104.2 C105.2 C106.2 C107.2 CR10.1 J7.2 J7.3 J7.4 J7.5 U1.32(RFGND) U1.33(EGP) Y2.2(GND) Y2.4(GND) Z60.2 Z62.2 ; also on sheet 2 3 4
VDDR: C105.1 C106.1 C107.1 L1.1 U1.1(VDDR) U1.27(VDDR)
VDDS: B1.1 C99.1 C101.1 C102.1 C103.1 C104.1 R1.2 U1.6(VDDS) U1.14(VDDS) U1.25(VDDS) U1.30(VDDS)
DCDC: L1.2 U1.24(DCDC)
DIO3: R6.2 ; also on sheet 2
DIO4: R7.1 ; also on sheet 2
WMCU_RESET: C92.1 R1.1 U1.19(nRST) ; also on sheet 2 3
WMCU_SWDCK: U1.9(DIO17_SWDCK) ; also on sheet 2 3
WMCU_SWDIO: U1.8(DIO16_SWDIO) ; also on sheet 2 3
WMCU_VDD: B1.2 ; also on sheet 2 3
N3101199: C81.1 R6.1 U1.20(DIO3_X32_P) Y1.1
N3101441: C52.1 U1.29(X48_N) Y2.1
N3101453: C53.1 U1.28(X48_P) Y2.3
N3241033: C91.1 R7.2 U1.21(DIO4_X32_N) Y1.2
N3275984: CA1.2 J7.1
N3375988: C34.2 CA1.1 CA2.2 L33.2
N3377063: CA2.1 CR10.2 Z60.1 Z61.2
N3377070: ANT1.1(FEED) Z61.1 Z62.1
N3512302: C33.2 L33.1 U1.31(ANT)
N3566095: C9.1 U1.22(VDDD)

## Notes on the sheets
sheet 1
- Wireless MCU RF
- Wireless MCU IO block placed on page 2
- VDDS Decoupling Capacitors
- Pin 8
- Pin 17
- Pin 38
- Pin 31
- Placeholder for bead
- Pin 34
- Pin 1
- Place L1 and C105
  close to Pin 30
- Z1-Z3 for
  antenna matching
- BOM Generation notes:
  Following components not in library and replaced manually in BOM
  C9
  C33-C34
  C81
  C91, CA1
  C92 C99 C101 C102 C103 C106 C107
  C104 C105
  L1
  L33
